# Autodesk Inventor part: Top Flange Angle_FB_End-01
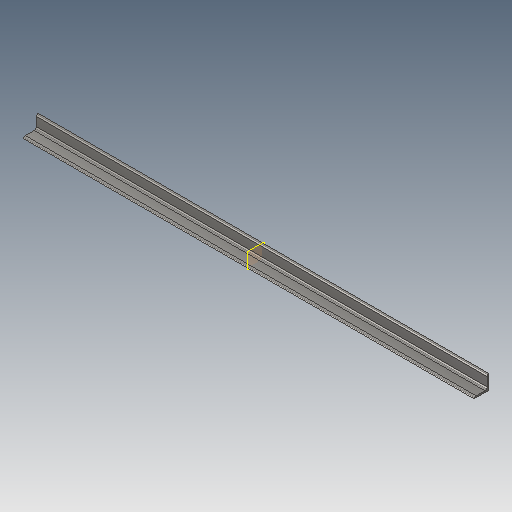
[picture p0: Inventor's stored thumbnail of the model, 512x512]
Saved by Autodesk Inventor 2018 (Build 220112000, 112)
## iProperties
Created: 2018-02
Part Number: Top Flange Angle_FB_End-01
Material: Steel, Mild
Document SubType Name: Modeling
Designer: STK
Density: 7.85 g/cm^3
Appearance: Semi-Polished
Mass: 216503 g
Surface Area: 46063.6 cm^2
Volume: 27580 cm^3
Author: STK
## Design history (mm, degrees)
sketch "Sketch1"
  geometry: L1 (5.875, -2.808)-(5.875, 149.592); L2 (21.319, 127.752)-(21.319, 35.8); L3 (136.435, 12.635)-(44.483, 12.635); L4 (158.275, -2.808)-(5.875, -2.808); A1 r 23.165 centre (-1.846, 127.752) between (21.319, 127.752) and (5.875, 149.592); A2 r 23.165 centre (44.483, 35.8) between (21.319, 35.8) and (44.483, 12.635); A3 r 23.165 centre (136.435, -10.53) between (158.275, -2.808) and (136.435, 12.635)
  constraints: 8 end point, 6 point on circle, 4 tangent, 3 centre point, 2 equal radius, 1 parallel, 1 perpendicular
  dimensions: "d5" = 23.1648 radius of A2 (derived); "d6" = 152.4 distance from line of L1.end L4 (= d3); "d3" = 152.4 distance from line of L4.start L1 (derived); "d1" = 15.4432 distance between parallel lines of L3 L4 (derived); "d0" = 15.4432 distance between parallel lines of L2 L1 (= d1)
feature "Angle_equal:1" sketch "Sketch1"
workplane "Work Plane1"
body "Solid1"
